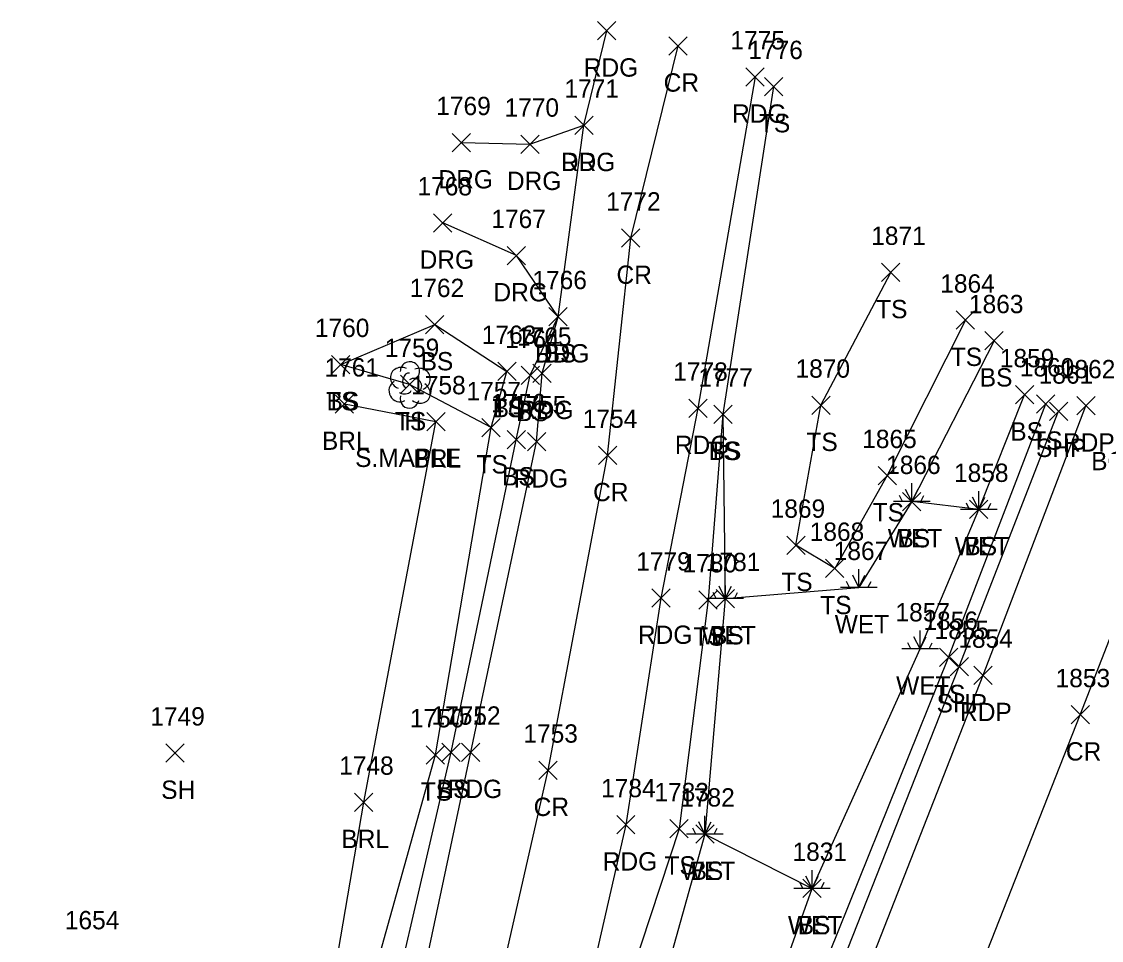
# Model space of a CAD drawing. Extents: x 1554917 to 1555870, y 813367 to 816333.
# Drawn here: x 1555214.2 to 1555332, y 814273.6 to 814373.9 of the extents above; entities that cross this region are included whole.
import ezdxf

# ---------------------------------------------------------------- set-up
doc = ezdxf.new("R2010")
doc.units = 0
for name, color, linetype in [('G_A', 7, 'Continuous'), ('L_A', 7, 'Continuous'), ('L_C', 7, 'Continuous'), ('L_I', 7, 'Continuous'), ('L_TIC', 7, 'Continuous'), ('LABL', 7, 'Continuous'), ('LELB', 7, 'Continuous'), ('LTD', 7, 'Continuous'), ('LWET', 7, 'Continuous'), ('P_A', 7, 'Continuous'), ('P_I', 7, 'Continuous'), ('P_TIC', 7, 'Continuous'), ('PET', 7, 'Continuous'), ('PEU', 7, 'Continuous'), ('PRC', 7, 'Continuous'), ('PSP', 7, 'Continuous'), ('R_A', 7, 'Continuous'), ('R_I', 7, 'Continuous'), ('R_TIC', 7, 'Continuous'), ('RDG', 7, 'Continuous')]:
    doc.layers.add(name, color=color, linetype=linetype)

msp = doc.modelspace()

# ---------------------------------------------------------------- linework, layer by layer
at = {"layer": 'L_TIC'}
for points in [[(1555295.24, 814365.8), (1555297.24, 814367.8)], [(1555297.24, 814365.8), (1555295.24, 814367.8)], [(1555308.03, 814345.52), (1555310.03, 814347.52)], [(1555310.03, 814345.52), (1555308.03, 814347.52)], [(1555271.72, 814340.69), (1555273.72, 814342.69)], [(1555273.72, 814340.69), (1555271.72, 814342.69)], [(1555316.18, 814340.31), (1555318.18, 814342.31)], [(1555318.18, 814340.31), (1555316.18, 814342.31)], [(1555258.27, 814339.83), (1555260.27, 814341.83)], [(1555260.27, 814339.83), (1555258.27, 814341.83)], [(1555319.31, 814338.07), (1555321.31, 814340.07)], [(1555321.31, 814338.07), (1555319.31, 814340.07)], [(1555248.01, 814335.47), (1555250.01, 814337.47)], [(1555250.01, 814335.47), (1555248.01, 814337.47)], [(1555248.01, 814335.47), (1555250.01, 814337.47)], [(1555250.01, 814335.47), (1555248.01, 814337.47)], [(1555266.14, 814334.72), (1555268.14, 814336.72)], [(1555268.14, 814334.72), (1555266.14, 814336.72)], [(1555266.14, 814334.72), (1555268.14, 814336.72)], [(1555268.14, 814334.72), (1555266.14, 814336.72)], [(1555255.51, 814333.29), (1555257.51, 814335.29)], [(1555257.51, 814333.29), (1555255.51, 814335.29)], [(1555268.68, 814334.29), (1555270.68, 814336.29)], [(1555270.68, 814334.29), (1555268.68, 814336.29)], [(1555322.64, 814332.17), (1555324.64, 814334.17)], [(1555324.64, 814332.17), (1555322.64, 814334.17)], [(1555248.41, 814331.16), (1555250.41, 814333.16)], [(1555250.41, 814331.16), (1555248.41, 814333.16)], [(1555300.42, 814331.03), (1555302.42, 814333.03)], [(1555302.42, 814331.03), (1555300.42, 814333.03)], [(1555324.95, 814331.17), (1555326.95, 814333.17)], [(1555326.95, 814331.17), (1555324.95, 814333.17)], [(1555289.72, 814330.05), (1555291.72, 814332.05)], [(1555291.72, 814330.05), (1555289.72, 814332.05)], [(1555289.72, 814330.05), (1555291.72, 814332.05)], [(1555291.72, 814330.05), (1555289.72, 814332.05)], [(1555258.39, 814329.22), (1555260.39, 814331.22)], [(1555260.39, 814329.22), (1555258.39, 814331.22)], [(1555264.42, 814328.58), (1555266.42, 814330.58)], [(1555266.42, 814328.58), (1555264.42, 814330.58)], [(1555264.42, 814328.58), (1555266.42, 814330.58)], [(1555266.42, 814328.58), (1555264.42, 814330.58)], [(1555267.16, 814327.27), (1555269.16, 814329.27)], [(1555269.16, 814327.27), (1555267.16, 814329.27)], [(1555307.66, 814323.35), (1555309.66, 814325.35)], [(1555309.66, 814323.35), (1555307.66, 814325.35)], [(1555310.33, 814320.52), (1555312.33, 814322.52)], [(1555312.33, 814320.52), (1555310.33, 814322.52)], [(1555317.64, 814319.66), (1555319.64, 814321.66)], [(1555319.64, 814319.66), (1555317.64, 814321.66)], [(1555297.68, 814315.75), (1555299.68, 814317.75)], [(1555299.68, 814315.75), (1555297.68, 814317.75)], [(1555301.93, 814313.23), (1555303.93, 814315.23)], [(1555303.93, 814313.23), (1555301.93, 814315.23)], [(1555288.09, 814309.79), (1555290.09, 814311.79)], [(1555290.09, 814309.79), (1555288.09, 814311.79)], [(1555289.98, 814309.93), (1555291.98, 814311.93)], [(1555291.98, 814309.93), (1555289.98, 814311.93)], [(1555314.35, 814303.52), (1555316.35, 814305.52)], [(1555316.35, 814303.52), (1555314.35, 814305.52)], [(1555260.04, 814293.17), (1555262.04, 814295.17)], [(1555262.04, 814293.17), (1555260.04, 814295.17)], [(1555229.93, 814293.08), (1555231.93, 814295.08)], [(1555231.93, 814293.08), (1555229.93, 814295.08)], [(1555258.33, 814292.88), (1555260.33, 814294.88)], [(1555260.33, 814292.88), (1555258.33, 814294.88)], [(1555250.52, 814287.71), (1555252.52, 814289.71)], [(1555252.52, 814287.71), (1555250.52, 814289.71)], [(1555284.93, 814284.82), (1555286.93, 814286.82)], [(1555286.93, 814284.82), (1555284.93, 814286.82)], [(1555287.75, 814284.24), (1555289.75, 814286.24)], [(1555289.75, 814284.24), (1555287.75, 814286.24)], [(1555299.44, 814278.31), (1555301.44, 814280.31)], [(1555301.44, 814278.31), (1555299.44, 814280.31)]]:
    msp.add_lwpolyline(points, dxfattribs=at)
at = {"layer": 'LABL'}
msp.add_lwpolyline([(1555170.56, 814225.07), (1555196.9, 814222.93), (1555217.8, 814222.5), (1555221.03, 814223.42), (1555235.64, 814238.62), (1555246.25, 814257.84), (1555251.52, 814288.71), (1555259.39, 814330.22), (1555249.41, 814332.16)], dxfattribs=at)
at = {"layer": 'LELB'}
for points in [[(1555296.24, 814366.8), (1555290.72, 814331.05), (1555289.09, 814310.79), (1555285.93, 814285.82), (1555277.62, 814260.54), (1555271.26, 814235.38), (1555263.98, 814210.11), (1555261.73, 814196.47), (1555265.94, 814194.83), (1555271.45, 814194.97), (1555281.92, 814221.99), (1555299.07, 814264.14), (1555315.35, 814304.52), (1555325.95, 814332.17)], [(1555317.18, 814341.31), (1555308.66, 814324.35), (1555302.93, 814314.23), (1555298.68, 814316.75), (1555301.42, 814332.03), (1555309.03, 814346.52)], [(1555236.77, 814156.09), (1555225.98, 814163.26), (1555221.17, 814170.73), (1555224.53, 814184.88), (1555235.48, 814206.05), (1555233.86, 814222.69), (1555242.5, 814231.73), (1555251.85, 814254.47), (1555261.04, 814294.17), (1555268.16, 814328.27), (1555269.68, 814335.29), (1555272.72, 814341.69)], [(1555249.01, 814336.47), (1555259.27, 814340.83), (1555267.14, 814335.72)], [(1555320.31, 814339.07), (1555311.33, 814321.52)], [(1555265.42, 814329.58), (1555256.51, 814334.29), (1555249.01, 814336.47)], [(1555161.57, 813925.65), (1555168.92, 813938.89), (1555173.57, 813945.95), (1555174.16, 813952.01), (1555182.4, 813974.26), (1555190.04, 813992.11), (1555201.74, 814019.14), (1555212.19, 814045.46), (1555215.96, 814054.45), (1555221.93, 814072.78), (1555233.01, 814105.58), (1555244.12, 814126.91), (1555239.17, 814141.42), (1555241.48, 814149.75), (1555239.8, 814159.84), (1555236.73, 814168.01), (1555231.65, 814185.57), (1555238.6, 814201.71), (1555239.91, 814224.12), (1555242.5, 814231.73), (1555248.59, 814255.34), (1555259.33, 814293.88), (1555265.42, 814329.58), (1555267.14, 814335.72)], [(1555318.64, 814320.66), (1555323.64, 814333.17)], [(1555290.72, 814331.05), (1555290.98, 814310.93)], [(1555288.75, 814285.24), (1555281.61, 814259.69), (1555272.83, 814234.77), (1555266.17, 814210.24), (1555264.49, 814198.29), (1555266.03, 814197.26), (1555266.73, 814197.03), (1555278.25, 814222.88), (1555295.68, 814265.95), (1555300.44, 814279.31)]]:
    msp.add_lwpolyline(points, dxfattribs=at)
at = {"layer": 'LTD'}
msp.add_line((1555256.51, 814334.29), (1555256.51, 814334.29), dxfattribs=at)
msp.add_line((1555256.51, 814334.29), (1555256.51, 814334.29), dxfattribs=at)
msp.add_arc((1555256.55, 814335.72), 1.05, 335.5272, 180.9563, dxfattribs=at)
for centre, major_axis, ratio, start_param, end_param in [((1555255.72, 814334.96), (1.21, -0.51), 0.895232, 1.570796, 4.712389), ((1555256.3, 814334.75), (-0.208, -0.792), 0.645439, 3.141593, 6.283185), ((1555257.55, 814334.87), (-1.14, -0.48), 0.949671, 1.570796, 4.712389), ((1555255.42, 814333.58), (0.58, -1.04), 0.959034, 3.141593, 6.283185), ((1555257.01, 814334.12), (-0.5, 0.667), 0.989748, 3.141593, 6.283185), ((1555257.51, 814333.46), (-1.09, 0.79), 0.841452, 1.570796, 4.712389), ((1555256.51, 814332.79), (0.26, 1.06), 0.942809, 1.570796, 4.712389), ((1555256.05, 814333.54), (-0.625, -0.083), 0.423636, 0, 3.141593)]:
    msp.add_ellipse(centre, major_axis=major_axis, ratio=ratio, start_param=start_param, end_param=end_param, dxfattribs=at)
at = {"layer": 'LWET'}
for p, q in [((1555311.33, 814321.52), (1555311.33, 814323.52)), ((1555311.33, 814321.52), (1555310.66, 814322.85)), ((1555311.33, 814321.52), (1555311.99, 814322.85)), ((1555318.64, 814320.66), (1555318.64, 814322.66)), ((1555313.33, 814321.52), (1555309.33, 814321.52)), ((1555310.33, 814321.52), (1555309.99, 814322.19)), ((1555312.33, 814321.52), (1555312.66, 814322.19)), ((1555317.64, 814320.66), (1555317.3, 814321.33)), ((1555318.64, 814320.66), (1555317.97, 814321.99)), ((1555318.64, 814320.66), (1555319.3, 814321.99)), ((1555319.64, 814320.66), (1555319.97, 814321.33)), ((1555320.64, 814320.66), (1555316.64, 814320.66)), ((1555305.55, 814312.14), (1555305.55, 814314.14)), ((1555305.55, 814312.14), (1555305.55, 814314.14)), ((1555290.98, 814310.93), (1555290.98, 814312.93)), ((1555290.98, 814310.93), (1555290.98, 814312.93)), ((1555304.55, 814312.14), (1555304.21, 814312.81)), ((1555304.55, 814312.14), (1555304.21, 814312.81)), ((1555305.55, 814312.14), (1555304.88, 814313.48)), ((1555305.55, 814312.14), (1555304.88, 814313.48)), ((1555305.55, 814312.14), (1555306.21, 814313.48)), ((1555305.55, 814312.14), (1555306.21, 814313.48)), ((1555306.55, 814312.14), (1555306.88, 814312.81)), ((1555306.55, 814312.14), (1555306.88, 814312.81)), ((1555290.98, 814310.93), (1555290.31, 814312.27)), ((1555290.98, 814310.93), (1555290.31, 814312.27)), ((1555290.98, 814310.93), (1555291.65, 814312.27)), ((1555290.98, 814310.93), (1555291.65, 814312.27)), ((1555307.55, 814312.14), (1555303.55, 814312.14)), ((1555307.55, 814312.14), (1555303.55, 814312.14)), ((1555292.98, 814310.93), (1555288.98, 814310.93)), ((1555292.98, 814310.93), (1555288.98, 814310.93)), ((1555289.98, 814310.93), (1555289.65, 814311.6)), ((1555289.98, 814310.93), (1555289.65, 814311.6)), ((1555291.98, 814310.93), (1555292.31, 814311.6)), ((1555291.98, 814310.93), (1555292.31, 814311.6)), ((1555312.24, 814305.44), (1555312.24, 814307.44)), ((1555311.24, 814305.44), (1555310.91, 814306.1)), ((1555312.24, 814305.44), (1555311.57, 814306.77)), ((1555312.24, 814305.44), (1555312.91, 814306.77)), ((1555313.24, 814305.44), (1555313.57, 814306.1)), ((1555314.24, 814305.44), (1555310.24, 814305.44)), ((1555288.75, 814285.24), (1555288.75, 814287.24)), ((1555287.75, 814285.24), (1555287.42, 814285.9)), ((1555288.75, 814285.24), (1555288.08, 814286.57)), ((1555288.75, 814285.24), (1555289.42, 814286.57)), ((1555289.75, 814285.24), (1555290.08, 814285.9)), ((1555290.75, 814285.24), (1555286.75, 814285.24)), ((1555300.44, 814279.31), (1555300.44, 814281.31)), ((1555299.44, 814279.31), (1555299.1, 814279.98)), ((1555300.44, 814279.31), (1555299.77, 814280.64)), ((1555300.44, 814279.31), (1555301.1, 814280.64)), ((1555301.44, 814279.31), (1555301.77, 814279.98)), ((1555302.44, 814279.31), (1555298.44, 814279.31))]:
    msp.add_line(p, q, dxfattribs=at)
for points in [[(1555290.98, 814310.93), (1555288.75, 814285.24), (1555300.44, 814279.31), (1555312.24, 814305.44), (1555318.64, 814320.66), (1555311.33, 814321.52), (1555305.55, 814312.14)], [(1555290.98, 814310.93), (1555305.55, 814312.14)]]:
    msp.add_lwpolyline(points, dxfattribs=at)
at = {"layer": 'P_TIC'}
for points in [[(1555277.04, 814371.88), (1555279.04, 814373.88)], [(1555279.04, 814371.88), (1555277.04, 814373.88)], [(1555284.82, 814370.24), (1555286.82, 814372.24)], [(1555286.82, 814370.24), (1555284.82, 814372.24)], [(1555293.23, 814366.85), (1555295.23, 814368.85)], [(1555295.23, 814366.85), (1555293.23, 814368.85)], [(1555274.54, 814361.57), (1555276.54, 814363.57)], [(1555276.54, 814361.57), (1555274.54, 814363.57)], [(1555279.66, 814349.27), (1555281.66, 814351.27)], [(1555281.66, 814349.27), (1555279.66, 814351.27)], [(1555271.72, 814340.69), (1555273.72, 814342.69)], [(1555273.72, 814340.69), (1555271.72, 814342.69)], [(1555269.98, 814334.52), (1555271.98, 814336.52)], [(1555271.98, 814334.52), (1555269.98, 814336.52)], [(1555329.34, 814330.97), (1555331.34, 814332.97)], [(1555331.34, 814330.97), (1555329.34, 814332.97)], [(1555286.98, 814330.7), (1555288.98, 814332.7)], [(1555288.98, 814330.7), (1555286.98, 814332.7)], [(1555326.36, 814330.38), (1555328.36, 814332.38)], [(1555328.36, 814330.38), (1555326.36, 814332.38)], [(1555269.38, 814327.05), (1555271.38, 814329.05)], [(1555271.38, 814327.05), (1555269.38, 814329.05)], [(1555277.12, 814325.56), (1555279.12, 814327.56)], [(1555279.12, 814325.56), (1555277.12, 814327.56)], [(1555282.95, 814309.99), (1555284.95, 814311.99)], [(1555284.95, 814309.99), (1555282.95, 814311.99)], [(1555315.51, 814302.51), (1555317.51, 814304.51)], [(1555317.51, 814302.51), (1555315.51, 814304.51)], [(1555318.11, 814301.56), (1555320.11, 814303.56)], [(1555320.11, 814301.56), (1555318.11, 814303.56)], [(1555328.72, 814297.26), (1555330.72, 814299.26)], [(1555330.72, 814297.26), (1555328.72, 814299.26)], [(1555262.19, 814293.17), (1555264.19, 814295.17)], [(1555264.19, 814293.17), (1555262.19, 814295.17)], [(1555270.63, 814291.21), (1555272.63, 814293.21)], [(1555272.63, 814291.21), (1555270.63, 814293.21)], [(1555279.12, 814285.26), (1555281.12, 814287.26)], [(1555281.12, 814285.26), (1555279.12, 814287.26)]]:
    msp.add_lwpolyline(points, dxfattribs=at)
at = {"layer": 'PET'}
msp.add_lwpolyline([(1555161.36, 813900.53), (1555183.5, 813956.99), (1555189.63, 813971.7), (1555196.36, 813987.75), (1555203.89, 814008), (1555206.01, 814012.95), (1555218.07, 814043.52), (1555227.32, 814068.19), (1555240.79, 814103.21), (1555254.41, 814137.22), (1555273.72, 814186.43), (1555286.72, 814219.57), (1555303.34, 814262.32), (1555319.11, 814302.56), (1555330.34, 814331.97)], dxfattribs=at)
at = {"layer": 'PEU'}
for points in [[(1555247.26, 814170.29), (1555242.05, 814198.92), (1555245.04, 814226.75), (1555254.52, 814253.2), (1555263.19, 814294.17), (1555270.38, 814328.05), (1555270.98, 814335.52), (1555272.72, 814341.69), (1555275.54, 814362.57), (1555278.04, 814372.88)], [(1555294.23, 814367.85), (1555287.98, 814331.7), (1555283.95, 814310.99), (1555280.12, 814286.26), (1555274.45, 814261.4), (1555268.32, 814236.36), (1555261.1, 814211.27), (1555259.38, 814197.47), (1555260.71, 814192.35)]]:
    msp.add_lwpolyline(points, dxfattribs=at)
at = {"layer": 'PRC'}
for points in [[(1555261.62, 814162.67), (1555259.2, 814167.45), (1555253.74, 814178.64), (1555251.43, 814189.46), (1555251.3, 814201.27), (1555254.86, 814223.68), (1555261.92, 814249.47), (1555271.63, 814292.21), (1555278.12, 814326.56), (1555280.66, 814350.27), (1555285.82, 814371.24)], [(1554976.76, 813382.18), (1554992.84, 813427.9), (1555014.07, 813486.01), (1555030.62, 813532.31), (1555046.37, 813573.08), (1555064.69, 813621.19), (1555082.41, 813667.53), (1555112.1, 813744.1), (1555110.69, 813739.79), (1555136.16, 813805.74), (1555152.52, 813846.93), (1555172.03, 813896.18), (1555193.96, 813951.2), (1555206.37, 813983.4), (1555218.13, 814013.22), (1555228.65, 814039.26), (1555237.93, 814064.31), (1555252.22, 814099.76), (1555265.8, 814135.89), (1555275.26, 814160.09), (1555297.17, 814214.77), (1555313.83, 814257.94), (1555329.72, 814298.26), (1555342.03, 814329.92)]]:
    msp.add_lwpolyline(points, dxfattribs=at)
at = {"layer": 'PSP'}
msp.add_lwpolyline([(1555160.79, 813906.47), (1555173.05, 813937.33), (1555179.42, 813953.63), (1555181.24, 813957.84), (1555186.72, 813973.16), (1555194.02, 813990.9), (1555204.38, 814016.29), (1555205.03, 814017.75), (1555215.29, 814044.5), (1555224.66, 814068.93), (1555238.68, 814103.48), (1555248.96, 814130.73), (1555261.62, 814162.67), (1555270.99, 814187.05), (1555283.98, 814220.8), (1555300.65, 814263.34), (1555316.51, 814303.51), (1555327.36, 814331.38)], dxfattribs=at)
at = {"layer": 'R_TIC'}
for points in [[(1555274.54, 814361.57), (1555276.54, 814363.57)], [(1555276.54, 814361.57), (1555274.54, 814363.57)], [(1555261.18, 814359.68), (1555263.18, 814361.68)], [(1555263.18, 814359.68), (1555261.18, 814361.68)], [(1555268.65, 814359.51), (1555270.65, 814361.51)], [(1555270.65, 814359.51), (1555268.65, 814361.51)], [(1555259.13, 814350.92), (1555261.13, 814352.92)], [(1555261.13, 814350.92), (1555259.13, 814352.92)], [(1555267.18, 814347.36), (1555269.18, 814349.36)], [(1555269.18, 814347.36), (1555267.18, 814349.36)], [(1555271.72, 814340.69), (1555273.72, 814342.69)], [(1555273.72, 814340.69), (1555271.72, 814342.69)]]:
    msp.add_lwpolyline(points, dxfattribs=at)
at = {"layer": 'RDG'}
for points in [[(1555262.18, 814360.68), (1555269.65, 814360.51), (1555275.54, 814362.57)], [(1555272.72, 814341.69), (1555268.18, 814348.36), (1555260.13, 814351.92)]]:
    msp.add_lwpolyline(points, dxfattribs=at)

# ---------------------------------------------------------------- texts
at = {"layer": 'G_A'}
msp.add_text('BORING', height=2, dxfattribs=at).set_placement((1555330.91, 814324.94))
at = {"layer": 'L_A'}
for s, p in [('TS', (1555294.65, 814361.8)), ('TS', (1555307.44, 814341.52)), ('BS', (1555257.72, 814335.83)), ('BS', (1555271.16, 814336.69)), ('TS', (1555315.59, 814336.31)), ('BS', (1555318.75, 814334.07)), ('TS', (1555247.42, 814331.47)), ('BS', (1555247.45, 814331.47)), ('TS', (1555265.55, 814330.72)), ('BS', (1555265.58, 814330.72)), ('BS', (1555268.12, 814330.29)), ('TS', (1555254.92, 814329.29)), ('H', (1555255.94, 814329.29)), ('BS', (1555322.08, 814328.17)), ('BRL', (1555246.95, 814327.16)), ('TS', (1555299.83, 814327.03)), ('TS', (1555324.36, 814327.17)), ('BRL', (1555256.93, 814325.22)), ('TS', (1555289.13, 814326.05)), ('BS', (1555289.16, 814326.05)), ('TS', (1555263.83, 814324.58)), ('TS', (1555263.83, 814324.58)), ('BS', (1555266.6, 814323.27)), ('TS', (1555307.06, 814319.35)), ('WET', (1555308.71, 814316.52)), ('BS', (1555309.77, 814316.52)), ('WET', (1555316.02, 814315.66)), ('BS', (1555317.08, 814315.66)), ('TS', (1555297.09, 814311.75)), ('TS', (1555301.34, 814309.23)), ('WET', (1555302.92, 814307.14)), ('WET', (1555302.92, 814307.14)), ('TS', (1555287.49, 814305.79)), ('WET', (1555288.36, 814305.93)), ('WET', (1555288.36, 814305.93)), ('BS', (1555289.42, 814305.93)), ('WET', (1555309.62, 814300.44)), ('TS', (1555313.76, 814299.52)), ('SH', (1555229.41, 814289.08)), ('TS', (1555257.74, 814288.88)), ('BS', (1555259.48, 814289.17)), ('BRL', (1555249.07, 814283.71)), ('TS', (1555284.34, 814280.82)), ('WET', (1555286.13, 814280.24)), ('BS', (1555287.19, 814280.24)), ('WET', (1555297.81, 814274.31)), ('BS', (1555298.88, 814274.31))]:
    msp.add_text(s, height=2, dxfattribs=at).set_placement(p)
at = {"layer": 'L_C'}
msp.add_text('S.MAPLE', height=2, dxfattribs=at).set_placement((1555250.57, 814325.29))
at = {"layer": 'L_I'}
for s, p in [('1776', (1555293.49, 814369.8)), ('1871', (1555306.9, 814349.52)), ('1762', (1555256.53, 814343.83)), ('1766', (1555269.92, 814344.69)), ('1864', (1555314.44, 814344.31)), ('1863', (1555317.57, 814342.07)), ('1760', (1555246.18, 814339.47)), ('1760', (1555246.18, 814339.47)), ('1763', (1555264.4, 814338.72)), ('1763', (1555264.4, 814338.72)), ('1764', (1555266.94, 814338.29)), ('1759', (1555253.81, 814337.29)), ('1759', (1555253.81, 814337.29)), ('1859', (1555320.94, 814336.17)), ('1761', (1555247.23, 814335.16)), ('1870', (1555298.64, 814335.03)), ('1860', (1555323.12, 814335.17)), ('1758', (1555256.69, 814333.22)), ('1777', (1555288.03, 814334.05)), ('1777', (1555288.03, 814334.05)), ('1757', (1555262.73, 814332.58)), ('1757', (1555262.73, 814332.58)), ('1756', (1555265.41, 814331.27)), ('1865', (1555305.92, 814327.35)), ('1866', (1555308.53, 814324.52)), ('1866', (1555308.53, 814324.52)), ('1858', (1555315.94, 814323.66)), ('1858', (1555315.94, 814323.66)), ('1869', (1555295.93, 814319.75)), ('1868', (1555300.19, 814317.23)), ('1867', (1555302.81, 814315.14)), ('1867', (1555302.81, 814315.14)), ('1780', (1555286.31, 814313.79)), ('1781', (1555288.85, 814313.93)), ('1781', (1555288.85, 814313.93)), ('1781', (1555288.85, 814313.93)), ('1857', (1555309.55, 814308.44)), ('1856', (1555312.6, 814307.52)), ('1749', (1555228.22, 814297.08)), ('1750', (1555256.55, 814296.88)), ('1751', (1555258.92, 814297.17)), ('1748', (1555248.83, 814291.71)), ('1783', (1555283.24, 814288.82)), ('1782', (1555286.06, 814288.24)), ('1782', (1555286.06, 814288.24)), ('1831', (1555298.31, 814282.31)), ('1831', (1555298.31, 814282.31)), ('1654', (1555218.89, 814274.85))]:
    msp.add_text(s, height=2, dxfattribs=at).set_placement(p)
at = {"layer": 'P_A'}
for s, p in [('RDG', (1555275.53, 814367.88)), ('CR', (1555284.25, 814366.24)), ('RDG', (1555291.72, 814362.85)), ('RDG', (1555273.03, 814357.57)), ('CR', (1555279.1, 814345.27)), ('RDG', (1555270.2, 814336.69)), ('RDG', (1555268.46, 814330.52)), ('RDG', (1555285.47, 814326.7)), ('SHP', (1555324.89, 814326.38)), ('RDP', (1555327.83, 814326.97)), ('RDG', (1555267.87, 814323.05)), ('CR', (1555276.55, 814321.56)), ('RDG', (1555281.44, 814305.99)), ('SHP', (1555314.04, 814298.51)), ('RDP', (1555316.6, 814297.56)), ('CR', (1555328.15, 814293.26)), ('RDG', (1555260.68, 814289.17)), ('CR', (1555270.06, 814287.21)), ('RDG', (1555277.6, 814281.26))]:
    msp.add_text(s, height=2, dxfattribs=at).set_placement(p)
at = {"layer": 'P_I'}
for s, p in [('1775', (1555291.53, 814370.85)), ('1771', (1555273.42, 814365.57)), ('1772', (1555277.97, 814353.27)), ('1766', (1555269.92, 814344.69)), ('1765', (1555268.24, 814338.52)), ('1778', (1555285.29, 814334.7)), ('1861', (1555325.18, 814334.38)), ('1862', (1555327.6, 814334.97)), ('1755', (1555267.68, 814331.05)), ('1754', (1555275.42, 814329.56)), ('1779', (1555281.25, 814313.99)), ('1855', (1555313.82, 814306.51)), ('1854', (1555316.41, 814305.56)), ('1853', (1555327.03, 814301.26)), ('1752', (1555260.5, 814297.17)), ('1753', (1555268.94, 814295.21)), ('1784', (1555277.42, 814289.26))]:
    msp.add_text(s, height=2, dxfattribs=at).set_placement(p)
at = {"layer": 'R_A'}
for p in [(1555273.03, 814357.57), (1555259.67, 814355.68), (1555267.14, 814355.51), (1555257.61, 814346.92), (1555265.67, 814343.36), (1555270.2, 814336.69)]:
    msp.add_text('DRG', height=2, dxfattribs=at).set_placement(p)
at = {"layer": 'R_I'}
for s, p in [('1771', (1555273.42, 814365.57)), ('1769', (1555259.43, 814363.68)), ('1770', (1555266.88, 814363.51)), ('1768', (1555257.38, 814354.92)), ('1767', (1555265.44, 814351.36)), ('1766', (1555269.92, 814344.69))]:
    msp.add_text(s, height=2, dxfattribs=at).set_placement(p)

doc.saveas('drawing.dxf')
